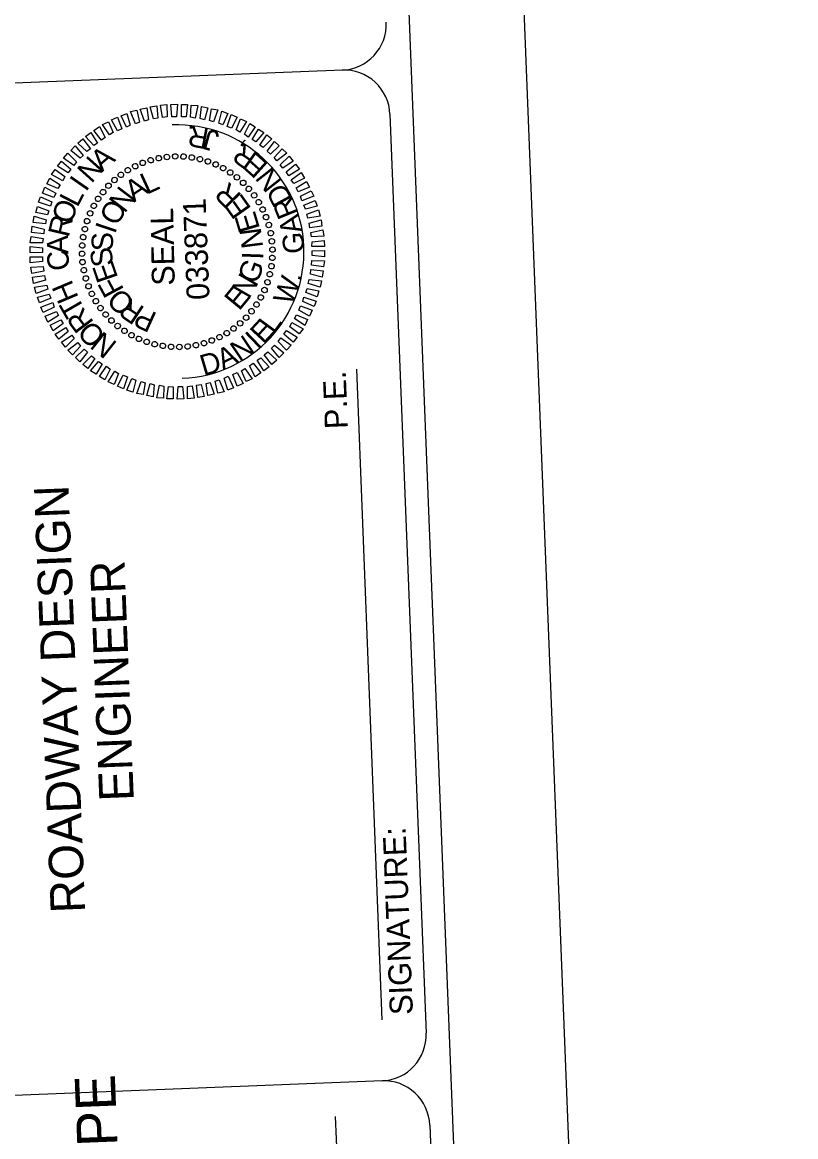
# Model space of a CAD drawing. Extents: x 1624323 to 1631382, y 753034 to 769560.
# Drawn here: x 1630364 to 1631382, y 765176 to 766642 of the extents above; entities that cross this region are included whole.
import ezdxf

# ---------------------------------------------------------------- set-up
doc = ezdxf.new("R2010")
doc.units = 0
for name, color, linetype in [('Scratch_Level_0', 7, 'Continuous'), ('Sheet Data Field CELL', 7, 'Continuous'), ('Sheet Plot Border Outside CELL', 7, 'Continuous'), ('Sheet Professional Seal CELL', 7, 'Continuous'), ('Sheet Profile Grid Minor CELL', 7, 'Continuous'), ('Sheet Title CELL', 7, 'Continuous')]:
    doc.layers.add(name, color=color, linetype=linetype)

msp = doc.modelspace()

# ---------------------------------------------------------------- linework, layer by layer
at = {"layer": 'Scratch_Level_0'}
msp.add_arc((1630568, 766340.3), 166.8, 272.2582, 92.2582, dxfattribs=at)
at = {"layer": 'Sheet Plot Border Outside CELL'}
msp.add_lwpolyline([(1624322.9, 767519.9), (1624724.8, 757327.8), (1631382.3, 757590.3), (1630980.3, 767782.4)], close=True, dxfattribs=at)
at = {"layer": 'Sheet Professional Seal CELL'}
for p, q in [((1630543.6, 766463.1), (1630543.6, 766463.1)), ((1630554.3, 766465.1), (1630554.3, 766465.1)), ((1630565.3, 766465.7), (1630565.3, 766465.7)), ((1630576.3, 766465.4), (1630576.3, 766465.4)), ((1630587.1, 766464.1), (1630587.1, 766464.1)), ((1630512.5, 766452.9), (1630512.5, 766452.9)), ((1630522.3, 766457.3), (1630522.3, 766457.3)), ((1630532.7, 766460.7), (1630532.7, 766460.7)), ((1630597.7, 766462.3), (1630597.7, 766462.3)), ((1630608.3, 766459.2), (1630608.3, 766459.2)), ((1630618.5, 766455.1), (1630618.5, 766455.1)), ((1630628.4, 766450.5), (1630628.4, 766450.5)), ((1630485.2, 766434.8), (1630485.2, 766434.8)), ((1630493.7, 766441.4), (1630493.7, 766441.4)), ((1630502.9, 766447.5), (1630502.9, 766447.5)), ((1630637.7, 766444.6), (1630637.7, 766444.6)), ((1630646.7, 766438.2), (1630646.7, 766438.2)), ((1630477.2, 766427), (1630477.2, 766427)), ((1630654.7, 766431), (1630654.7, 766431)), ((1630662.5, 766423), (1630662.5, 766423)), ((1630463.6, 766409.9), (1630463.6, 766409.9)), ((1630470, 766419), (1630470, 766419)), ((1630669.1, 766414.5), (1630669.1, 766414.5)), ((1630675.2, 766405.3), (1630675.2, 766405.3)), ((1630453.1, 766390.8), (1630453.1, 766390.8)), ((1630457.8, 766400.7), (1630457.8, 766400.7)), ((1630680.6, 766395.7), (1630680.6, 766395.7)), ((1630449, 766380.6), (1630449, 766380.6)), ((1630685, 766385.9), (1630685, 766385.9)), ((1630688.4, 766375.5), (1630688.4, 766375.5)), ((1630446, 766370), (1630446, 766370)), ((1630690.9, 766364.6), (1630690.9, 766364.6)), ((1630442.8, 766348.6), (1630442.8, 766348.6)), ((1630444.1, 766359.4), (1630444.1, 766359.4)), ((1630692.8, 766353.9), (1630692.8, 766353.9)), ((1630442.5, 766337.6), (1630442.5, 766337.6)), ((1630568, 766340.3), (1630568, 766340.3)), ((1630693.1, 766331.9), (1630693.1, 766331.9)), ((1630693.5, 766342.9), (1630693.5, 766342.9)), ((1630443.2, 766326.6), (1630443.2, 766326.6)), ((1630691.8, 766321.1), (1630691.8, 766321.1)), ((1630445.1, 766315.9), (1630445.1, 766315.9)), ((1630447.5, 766305), (1630447.5, 766305)), ((1630690, 766310.5), (1630690, 766310.5)), ((1630450.9, 766294.6), (1630450.9, 766294.6)), ((1630682.8, 766289.7), (1630682.8, 766289.7)), ((1630686.9, 766299.9), (1630686.9, 766299.9)), ((1630455.3, 766284.8), (1630455.3, 766284.8)), ((1630460.7, 766275.2), (1630460.7, 766275.2)), ((1630678.2, 766279.8), (1630678.2, 766279.8)), ((1630466.8, 766266), (1630466.8, 766266)), ((1630665.9, 766261.5), (1630665.9, 766261.5)), ((1630672.3, 766270.6), (1630672.3, 766270.6)), ((1630473.4, 766257.5), (1630473.4, 766257.5)), ((1630481.2, 766249.5), (1630481.2, 766249.5)), ((1630650.8, 766245.7), (1630650.8, 766245.7)), ((1630658.7, 766253.5), (1630658.7, 766253.5)), ((1630489.3, 766242.3), (1630489.3, 766242.3)), ((1630498.3, 766235.9), (1630498.3, 766235.9)), ((1630507.5, 766230), (1630507.5, 766230)), ((1630633, 766233), (1630633, 766233)), ((1630642.3, 766239.1), (1630642.3, 766239.1)), ((1630517.5, 766225.4), (1630517.5, 766225.4)), ((1630527.6, 766221.3), (1630527.6, 766221.3)), ((1630538.3, 766218.2), (1630538.3, 766218.2)), ((1630548.8, 766216.4), (1630548.8, 766216.4)), ((1630559.7, 766215.1), (1630559.7, 766215.1)), ((1630570.7, 766214.8), (1630570.7, 766214.8)), ((1630581.7, 766215.4), (1630581.7, 766215.4)), ((1630592.3, 766217.4), (1630592.3, 766217.4)), ((1630603.2, 766219.8), (1630603.2, 766219.8)), ((1630613.6, 766223.2), (1630613.6, 766223.2)), ((1630623.5, 766227.6), (1630623.5, 766227.6))]:
    msp.add_line(p, q, dxfattribs=at)
for points in [[(1630501, 766504.2), (1630493.9, 766519.2), (1630501.5, 766522.3), (1630506.1, 766506.9)], [(1630512.8, 766508.7), (1630506.4, 766524.5), (1630514.6, 766526.3), (1630518, 766510.7)], [(1630524.7, 766512.2), (1630519.3, 766527.7), (1630527.7, 766529.6), (1630529.9, 766513.9)], [(1630536.6, 766514.9), (1630532.4, 766531), (1630540.9, 766532.1), (1630542.5, 766516.1)], [(1630548.5, 766516.9), (1630545.9, 766533), (1630554.3, 766533.9), (1630554.5, 766517.6)], [(1630561, 766517.6), (1630559.6, 766533.8), (1630568.1, 766534.2), (1630567, 766517.9)], [(1630573.5, 766517.9), (1630573.3, 766534.1), (1630581.6, 766533.9), (1630579.5, 766517.6)], [(1630585.5, 766517.1), (1630586.4, 766533.1), (1630594.9, 766532.5), (1630591.6, 766516.1)], [(1630598.3, 766515.6), (1630599.7, 766531.2), (1630608.3, 766529.7), (1630603.7, 766513.8)], [(1630610.5, 766512.8), (1630613.1, 766528.4), (1630621.4, 766527), (1630615.8, 766511)], [(1630622.6, 766509.5), (1630626.5, 766525.2), (1630634.4, 766522.3), (1630628, 766507)], [(1630478.9, 766493.9), (1630469.6, 766507.5), (1630477.2, 766511.1), (1630483.5, 766497)], [(1630489.4, 766499.3), (1630481.3, 766513.7), (1630489.2, 766517.3), (1630494.8, 766502)], [(1630633.8, 766505), (1630638.9, 766520.7), (1630646.8, 766517.2), (1630639.4, 766502.7)], [(1630645.5, 766500.4), (1630651.2, 766514.9), (1630659, 766511.5), (1630650.3, 766497.6)], [(1630656.5, 766494.9), (1630663.4, 766509.1), (1630670.6, 766504.4), (1630661.1, 766491)], [(1630458.1, 766480), (1630447.2, 766491.9), (1630454.2, 766496.9), (1630462.8, 766483.2)], [(1630468.1, 766486.9), (1630458.1, 766499.8), (1630465.4, 766504.8), (1630473, 766490.6)], [(1630666.7, 766487.8), (1630674.7, 766501.6), (1630682.1, 766497.1), (1630671.6, 766484.7)], [(1630676.5, 766480.6), (1630685.8, 766494), (1630692.5, 766488.8), (1630681.2, 766477.3)], [(1630440, 766463.1), (1630427.9, 766473.3), (1630433.6, 766479.6), (1630443.9, 766467)], [(1630448.7, 766472.2), (1630437, 766483.2), (1630443.5, 766488.7), (1630453.5, 766475.8)], [(1630686.4, 766472.3), (1630696.1, 766485.4), (1630702.1, 766479.4), (1630690.5, 766468.4)], [(1630431.6, 766453.7), (1630418.3, 766463.4), (1630424, 766469.7), (1630435.2, 766458.6)], [(1630695.4, 766464.4), (1630706, 766475.8), (1630712.2, 766470), (1630699.1, 766459.8)], [(1630703.6, 766454.7), (1630715.1, 766465.9), (1630720.6, 766459.4), (1630707, 766450.1)], [(1630424.3, 766443.9), (1630410.2, 766452.6), (1630415.4, 766459.3), (1630427.6, 766448.8)], [(1630711.4, 766445.5), (1630723.8, 766455.2), (1630728.8, 766448.9), (1630714.7, 766440.1)], [(1630410.8, 766423.4), (1630396.3, 766429.6), (1630400.3, 766437.2), (1630413.6, 766428.2)], [(1630417.2, 766433.4), (1630402.4, 766441.6), (1630407.3, 766448.3), (1630420, 766439)], [(1630718.1, 766434.7), (1630731.2, 766444.5), (1630735.5, 766436.9), (1630721.3, 766430.1)], [(1630405.5, 766411.7), (1630390.6, 766417.3), (1630393.7, 766425.2), (1630408.1, 766417.3)], [(1630724.5, 766424.2), (1630738.2, 766432.8), (1630742, 766425.2), (1630727, 766418.8)], [(1630730.2, 766413.5), (1630744.4, 766420.5), (1630747.7, 766413.1), (1630732, 766407.3)], [(1630401.2, 766400.2), (1630385.3, 766405.4), (1630388, 766412.5), (1630402.8, 766406)], [(1630734.7, 766401.4), (1630749.5, 766407.7), (1630752, 766400.1), (1630736.7, 766396.2)], [(1630397.2, 766388.8), (1630381.5, 766391.9), (1630383.7, 766399.8), (1630398.7, 766394.1)], [(1630738.4, 766389.5), (1630753.9, 766395.4), (1630756, 766386.9), (1630739.9, 766384.3)], [(1630394.4, 766376.7), (1630378.1, 766378.5), (1630379.7, 766387.1), (1630395.4, 766382)], [(1630741.6, 766377.6), (1630757.5, 766382.3), (1630758.5, 766374), (1630742.6, 766371.7)], [(1630392.2, 766363.8), (1630376.1, 766365.5), (1630377, 766373.8), (1630392.7, 766369.9)], [(1630743.6, 766365.7), (1630759.5, 766369.1), (1630760.8, 766360.6), (1630744.6, 766359.7)], [(1630390.4, 766339.3), (1630374.1, 766338.6), (1630374.1, 766346.9), (1630390.4, 766345.3)], [(1630390.6, 766351.8), (1630374.4, 766352.1), (1630375.5, 766360.4), (1630391.4, 766357.8)], [(1630745.4, 766353.3), (1630761.5, 766355.1), (1630761.6, 766346.9), (1630745.3, 766347.2)], [(1630390.6, 766327.3), (1630374.4, 766325.4), (1630374.3, 766333.6), (1630390.6, 766333.3)], [(1630745.6, 766341.3), (1630761.8, 766341.9), (1630761.9, 766333.6), (1630745.6, 766335.2)], [(1630392.3, 766314.8), (1630376.5, 766311.4), (1630375.1, 766319.9), (1630391.4, 766320.8)], [(1630743.8, 766316.7), (1630759.9, 766315), (1630758.9, 766306.8), (1630743.3, 766310.6)], [(1630745.3, 766328.7), (1630761.6, 766328.4), (1630760.4, 766320.1), (1630744.6, 766322.7)], [(1630394.3, 766302.9), (1630378.5, 766298.3), (1630377.4, 766306.5), (1630393.3, 766308.8)], [(1630741.5, 766303.8), (1630757.9, 766302), (1630756.2, 766293.4), (1630740.5, 766298.5)], [(1630397.5, 766291), (1630382, 766285.1), (1630379.9, 766293.6), (1630396.1, 766296.2)], [(1630738.8, 766291.7), (1630754.4, 766288.6), (1630752.2, 766280.7), (1630737.2, 766286.4)], [(1630401.3, 766279.1), (1630386.5, 766272.8), (1630383.9, 766280.5), (1630399.3, 766284.3)], [(1630405.7, 766267.1), (1630391.5, 766260), (1630388.2, 766267.4), (1630404, 766273.2)], [(1630734.7, 766280.3), (1630750.7, 766275.2), (1630748, 766268), (1630733.2, 766274.5)], [(1630411.4, 766256.3), (1630397.7, 766247.7), (1630393.9, 766255.3), (1630408.9, 766261.7)], [(1630730.4, 766268.8), (1630745.4, 766263.2), (1630742.2, 766255.3), (1630727.9, 766263.2)], [(1630417.8, 766245.8), (1630404.7, 766236), (1630400.4, 766243.6), (1630414.6, 766250.4)], [(1630718.8, 766247.1), (1630733.6, 766238.9), (1630728.6, 766232.2), (1630716, 766241.5)], [(1630725.1, 766257.1), (1630739.6, 766250.9), (1630735.7, 766243.3), (1630722.3, 766252.3)], [(1630424.5, 766235), (1630412.1, 766225.3), (1630407.1, 766231.6), (1630421.3, 766240.4)], [(1630432.4, 766225.8), (1630420.8, 766214.6), (1630415.3, 766221.1), (1630428.9, 766230.4)], [(1630711.7, 766236.6), (1630725.8, 766227.9), (1630720.5, 766221.2), (1630708.4, 766231.7)], [(1630440.5, 766216.1), (1630430, 766204.7), (1630423.7, 766210.5), (1630436.8, 766220.7)], [(1630695.9, 766217.4), (1630708.1, 766207.2), (1630702.3, 766200.9), (1630692.1, 766213.5)], [(1630704.3, 766226.8), (1630717.7, 766217.1), (1630711.9, 766210.8), (1630700.7, 766221.9)], [(1630449.6, 766208.2), (1630439.8, 766195.1), (1630433.9, 766201.1), (1630445.4, 766212.1)], [(1630459.4, 766199.9), (1630450.2, 766186.5), (1630443.5, 766191.7), (1630454.8, 766203.2)], [(1630677.8, 766200.5), (1630688.8, 766188.6), (1630681.7, 766183.6), (1630673.2, 766197.3)], [(1630687.3, 766208.4), (1630699, 766197.3), (1630692.4, 766191.8), (1630682.4, 766204.7)], [(1630469.2, 766192.7), (1630461.2, 766178.9), (1630453.8, 766183.4), (1630464.3, 766195.8)], [(1630479.5, 766185.6), (1630472.6, 766171.4), (1630465.4, 766176.1), (1630474.8, 766189.5)], [(1630657.1, 766186.6), (1630666.4, 766173), (1630658.8, 766169.4), (1630652.5, 766183.5)], [(1630667.8, 766193.6), (1630677.8, 766180.7), (1630670.5, 766175.7), (1630663, 766189.9)], [(1630490.5, 766180.1), (1630484.8, 766165.6), (1630476.9, 766169), (1630485.6, 766182.9)], [(1630502.2, 766175.5), (1630497, 766159.8), (1630489.1, 766163.3), (1630496.6, 766177.8)], [(1630513.4, 766171), (1630509.5, 766155.3), (1630501.6, 766158.2), (1630508, 766173.5)], [(1630623.2, 766171.8), (1630629.5, 766156), (1630621.3, 766154.2), (1630618, 766169.8)], [(1630635, 766176.3), (1630642.1, 766161.3), (1630634.4, 766158.2), (1630629.8, 766173.6)], [(1630646.6, 766181.2), (1630654.6, 766166.8), (1630646.8, 766163.2), (1630641.2, 766178.5)], [(1630525.5, 766167.7), (1630522.9, 766152.1), (1630514.5, 766153.5), (1630520.2, 766169.5)], [(1630537.6, 766164.9), (1630536.2, 766149.4), (1630527.7, 766150.8), (1630532.3, 766166.7)], [(1630550.4, 766163.4), (1630549.6, 766147.4), (1630541, 766148), (1630544.4, 766164.4)], [(1630562.5, 766162.6), (1630562.6, 766146.4), (1630554.3, 766146.6), (1630556.5, 766162.9)], [(1630575, 766162.9), (1630576.4, 766146.7), (1630567.9, 766146.3), (1630569, 766162.7)], [(1630587.4, 766163.6), (1630590.1, 766147.5), (1630581.6, 766146.6), (1630581.5, 766162.9)], [(1630599.4, 766165.6), (1630603.5, 766149.5), (1630595.1, 766148.4), (1630593.4, 766164.4)], [(1630611.3, 766168.3), (1630616.6, 766152.8), (1630608.2, 766150.9), (1630606.1, 766166.6)]]:
    msp.add_lwpolyline(points, close=True, dxfattribs=at)
for centre, major_axis in [((1630532.9, 766460.6), (-1.01, 3.46)), ((1630543.5, 766463.2), (-0.7, 3.53)), ((1630554.3, 766464.9), (-0.39, 3.58)), ((1630565.2, 766465.6), (-0.08, 3.6)), ((1630576.2, 766465.4), (0.23, 3.59)), ((1630587, 766464.2), (0.55, 3.56)), ((1630597.8, 766462.1), (0.86, 3.5)), ((1630502.9, 766447.4), (-1.87, 3.08)), ((1630512.5, 766452.7), (-1.59, 3.23)), ((1630522.5, 766457.1), (-1.31, 3.36)), ((1630608.3, 766459), (1.16, 3.41)), ((1630618.5, 766455), (1.45, 3.3)), ((1630628.3, 766450.2), (1.73, 3.16)), ((1630637.6, 766444.5), (2, 2.99)), ((1630485.3, 766434.5), (-2.37, 2.71)), ((1630493.8, 766441.4), (-2.13, 2.9)), ((1630646.5, 766438.1), (2.25, 2.81)), ((1630654.7, 766430.8), (2.49, 2.6)), ((1630470.2, 766418.7), (-2.81, 2.25)), ((1630477.4, 766427), (-2.6, 2.49)), ((1630662.2, 766422.9), (2.71, 2.37)), ((1630458, 766400.6), (-3.16, 1.73)), ((1630463.7, 766409.9), (-2.99, 2)), ((1630669.1, 766414.4), (2.9, 2.13)), ((1630675.2, 766405.3), (3.08, 1.87)), ((1630453.2, 766390.7), (-3.3, 1.45)), ((1630680.4, 766395.7), (3.23, 1.59)), ((1630684.8, 766385.7), (3.36, 1.31)), ((1630449.2, 766380.5), (-3.41, 1.16)), ((1630688.4, 766375.4), (3.46, 1.01)), ((1630444, 766359.3), (-3.56, 0.55)), ((1630446.2, 766370), (-3.5, 0.86)), ((1630691, 766364.7), (3.53, 0.7)), ((1630442.8, 766348.4), (-3.59, 0.23)), ((1630692.6, 766353.9), (3.58, 0.39)), ((1630693.3, 766343), (3.6, 0.08)), ((1630442.6, 766337.5), (-3.6, -0.08)), ((1630693.1, 766332.1), (3.59, -0.23)), ((1630443.3, 766326.6), (-3.58, -0.39)), ((1630445, 766315.8), (-3.53, -0.7)), ((1630691.9, 766321.2), (3.56, -0.55)), ((1630447.6, 766305.1), (-3.46, -1.01)), ((1630686.7, 766300), (3.41, -1.16)), ((1630689.8, 766310.5), (3.5, -0.86)), ((1630451.1, 766294.8), (-3.36, -1.31)), ((1630455.5, 766284.8), (-3.23, -1.59)), ((1630682.8, 766289.8), (3.3, -1.45)), ((1630460.8, 766275.2), (-3.08, -1.87)), ((1630672.3, 766270.6), (2.99, -2)), ((1630677.9, 766280), (3.16, -1.73)), ((1630466.9, 766266.1), (-2.9, -2.13)), ((1630473.7, 766257.6), (-2.71, -2.37)), ((1630665.8, 766261.8), (2.81, -2.25)), ((1630481.3, 766249.7), (-2.49, -2.6)), ((1630489.5, 766242.4), (-2.25, -2.81)), ((1630642.1, 766239.1), (2.13, -2.9)), ((1630650.7, 766246), (2.37, -2.71)), ((1630658.6, 766253.5), (2.6, -2.49)), ((1630498.3, 766236), (-2, -2.99)), ((1630507.7, 766230.3), (-1.73, -3.16)), ((1630517.5, 766225.5), (-1.45, -3.3)), ((1630623.5, 766227.8), (1.59, -3.23)), ((1630633, 766233.1), (1.87, -3.08)), ((1630527.7, 766221.5), (-1.16, -3.41)), ((1630538.2, 766218.4), (-0.86, -3.5)), ((1630548.9, 766216.3), (-0.55, -3.56)), ((1630559.8, 766215.1), (-0.23, -3.59)), ((1630570.7, 766214.9), (0.08, -3.6)), ((1630581.6, 766215.6), (0.39, -3.58)), ((1630592.5, 766217.3), (0.7, -3.53)), ((1630603.1, 766219.9), (1.01, -3.46)), ((1630613.4, 766223.4), (1.31, -3.36))]:
    msp.add_ellipse(centre, major_axis=major_axis, ratio=0.999708, dxfattribs=at)
at = {"layer": 'Sheet Title CELL'}
for p, q in [((1630785.3, 766579.2), (1629817, 766541)), ((1630837.9, 765329.4), (1630804.2, 766185.8)), ((1630837.9, 765249.1), (1629869.5, 765210.9)), ((1630813.6, 764256.4), (1630776.4, 765202.1))]:
    msp.add_line(p, q, dxfattribs=at)
for points in [[(1631188.8, 758655.6), (1630835.6, 767613)], [(1630895.9, 765312), (1630848.2, 766521.1)], [(1630968.7, 763466), (1630900.8, 765190.9)]]:
    msp.add_lwpolyline(points, dxfattribs=at)
for centre, start, end in [((1630782.6, 766639.7), 272.2582, 2.2582), ((1630787.4, 766518.7), 2.2582, 92.2582), ((1630835.1, 765309.6), 272.2582, 2.2582), ((1630839.9, 765188.6), 2.2582, 92.2582)]:
    msp.add_arc(centre, 60.6, start, end, dxfattribs=at)

# ---------------------------------------------------------------- texts
at = {"layer": 'Sheet Data Field CELL'}
msp.add_text('DANIEL W. GARDNER, JR., PE', height=52.999, rotation=92.2582, dxfattribs=at).set_placement((1630525.7, 764242.9))
at = {"layer": 'Sheet Professional Seal CELL'}
for s, height, rotation, p in [('N', 28.2, 48.0771, (1630454.9, 766429.1)), ('A', 28.2, 40.8753, (1630469, 766444.4)), ('I', 28.2, 55.2783, (1630447.6, 766418.1)), ('A', 28.2, 34.0185, (1630510.9, 766404.6)), ('L', 28.2, 24.659, (1630527.7, 766415)), ('N', 28.2, 52.7348, (1630498.5, 766389.8)), ('R', 28.2, 134.7396, (1630653.9, 766414.2)), ('O', 28.2, 69.6794, (1630428, 766375)), ('L', 28.2, 62.4791, (1630436.4, 766397.4)), ('O', 28.2, 62.0917, (1630489.1, 766372.7)), ('E', 28.2, 125.3823, (1630666.3, 766396.9)), ('SEAL', 29.99, 91.2582, (1630564.7, 766295.8)), ('E', 28.2, 106.67, (1630677.1, 766370.8)), ('R', 28.2, 76.8793, (1630424.9, 766358.1)), ('I', 28.2, 71.4478, (1630486, 766362.5)), ('A', 28.2, 91.2785, (1630424.7, 766337.1)), ('S', 28.2, 90.1586, (1630483.4, 766340.9)), ('N', 28.2, 97.3146, (1630681.1, 766346.2)), ('C', 28.2, 98.4781, (1630427, 766317.4)), ('S', 28.2, 99.5138, (1630484.3, 766322.9)), ('I', 28.2, 87.9594, (1630681, 766329.4)), ('E', 28.2, 108.8693, (1630490.3, 766305.9)), ('G', 28.2, 69.2484, (1630672.8, 766296.3)), ('H', 28.2, 112.8777, (1630438.5, 766279.9)), ('F', 28.2, 118.2252, (1630498.4, 766290.2)), ('N', 28.2, 59.8921, (1630662.3, 766276.9)), ('O', 28.2, 136.9394, (1630513.8, 766274.3)), ('E', 28.2, 50.5351, (1630649.4, 766261.4)), ('T', 28.2, 120.078, (1630447.4, 766263.9)), ('R', 28.2, 146.2978, (1630526.4, 766266.1)), ('R', 28.2, 127.2787, (1630459, 766247.4)), ('P', 28.2, 155.6571, (1630542.7, 766258.7)), ('O', 28.2, 134.4799, (1630475.2, 766230.8)), ('N', 28.2, 141.6817, (1630490.2, 766219.8))]:
    msp.add_text(s, height=height, rotation=rotation, dxfattribs=at).set_placement(p)
at = {"layer": 'Sheet Profile Grid Minor CELL'}
for s, height, rotation, p in [('R', 27.5, 169.6122, (1630611.1, 766501.9)), ('.', 27.5, 176.5387, (1630591.3, 766506)), ('J', 27.5, 164.7437, (1630624.7, 766497.7)), ('R', 27.5, 144.637, (1630675.4, 766468.6)), (',', 27.5, 151.5634, (1630659.1, 766480.6)), ('E', 27.5, 138.054, (1630689.4, 766455.4)), ('N', 27.5, 128.1223, (1630707.4, 766432.8)), ('D', 27.5, 118.9777, (1630720.4, 766409.4)), ('033871', 29.99, 92.2582, (1630610.5, 766277.4)), ('R', 27.5, 112.0512, (1630727.6, 766390.5)), ('A', 27.5, 103.8654, (1630733.1, 766367.3)), ('G', 27.5, 93.9337, (1630735.3, 766338.4)), ('W', 27.5, 69.1473, (1630719.1, 766268.4)), ('.', 27.5, 80.7534, (1630730.5, 766300.3)), ('E', 27.5, 47.309, (1630681.6, 766217.4)), ('L', 27.5, 53.892, (1630694.9, 766231.2)), ('N', 27.5, 33.8568, (1630649.9, 766194.3)), ('I', 27.5, 43.7885, (1630673.8, 766210.6)), ('A', 27.5, 25.671, (1630628.2, 766184.1)), ('D', 27.5, 16.5264, (1630602.7, 766176.5))]:
    msp.add_text(s, height=height, rotation=rotation, dxfattribs=at).set_placement(p)
at = {"layer": 'Sheet Title CELL'}
for s, height, p in [('P.E.', 30.28, (1630792.7, 766107.4)), ('ROADWAY DESIGN', 45.424, (1630446.8, 765470.7)), ('ENGINEER', 45.42, (1630510.8, 765617.8)), ('SIGNATURE:', 30.28, (1630878.3, 765336.4))]:
    msp.add_text(s, height=height, rotation=92.2582, dxfattribs=at).set_placement(p)

doc.saveas('drawing.dxf')
